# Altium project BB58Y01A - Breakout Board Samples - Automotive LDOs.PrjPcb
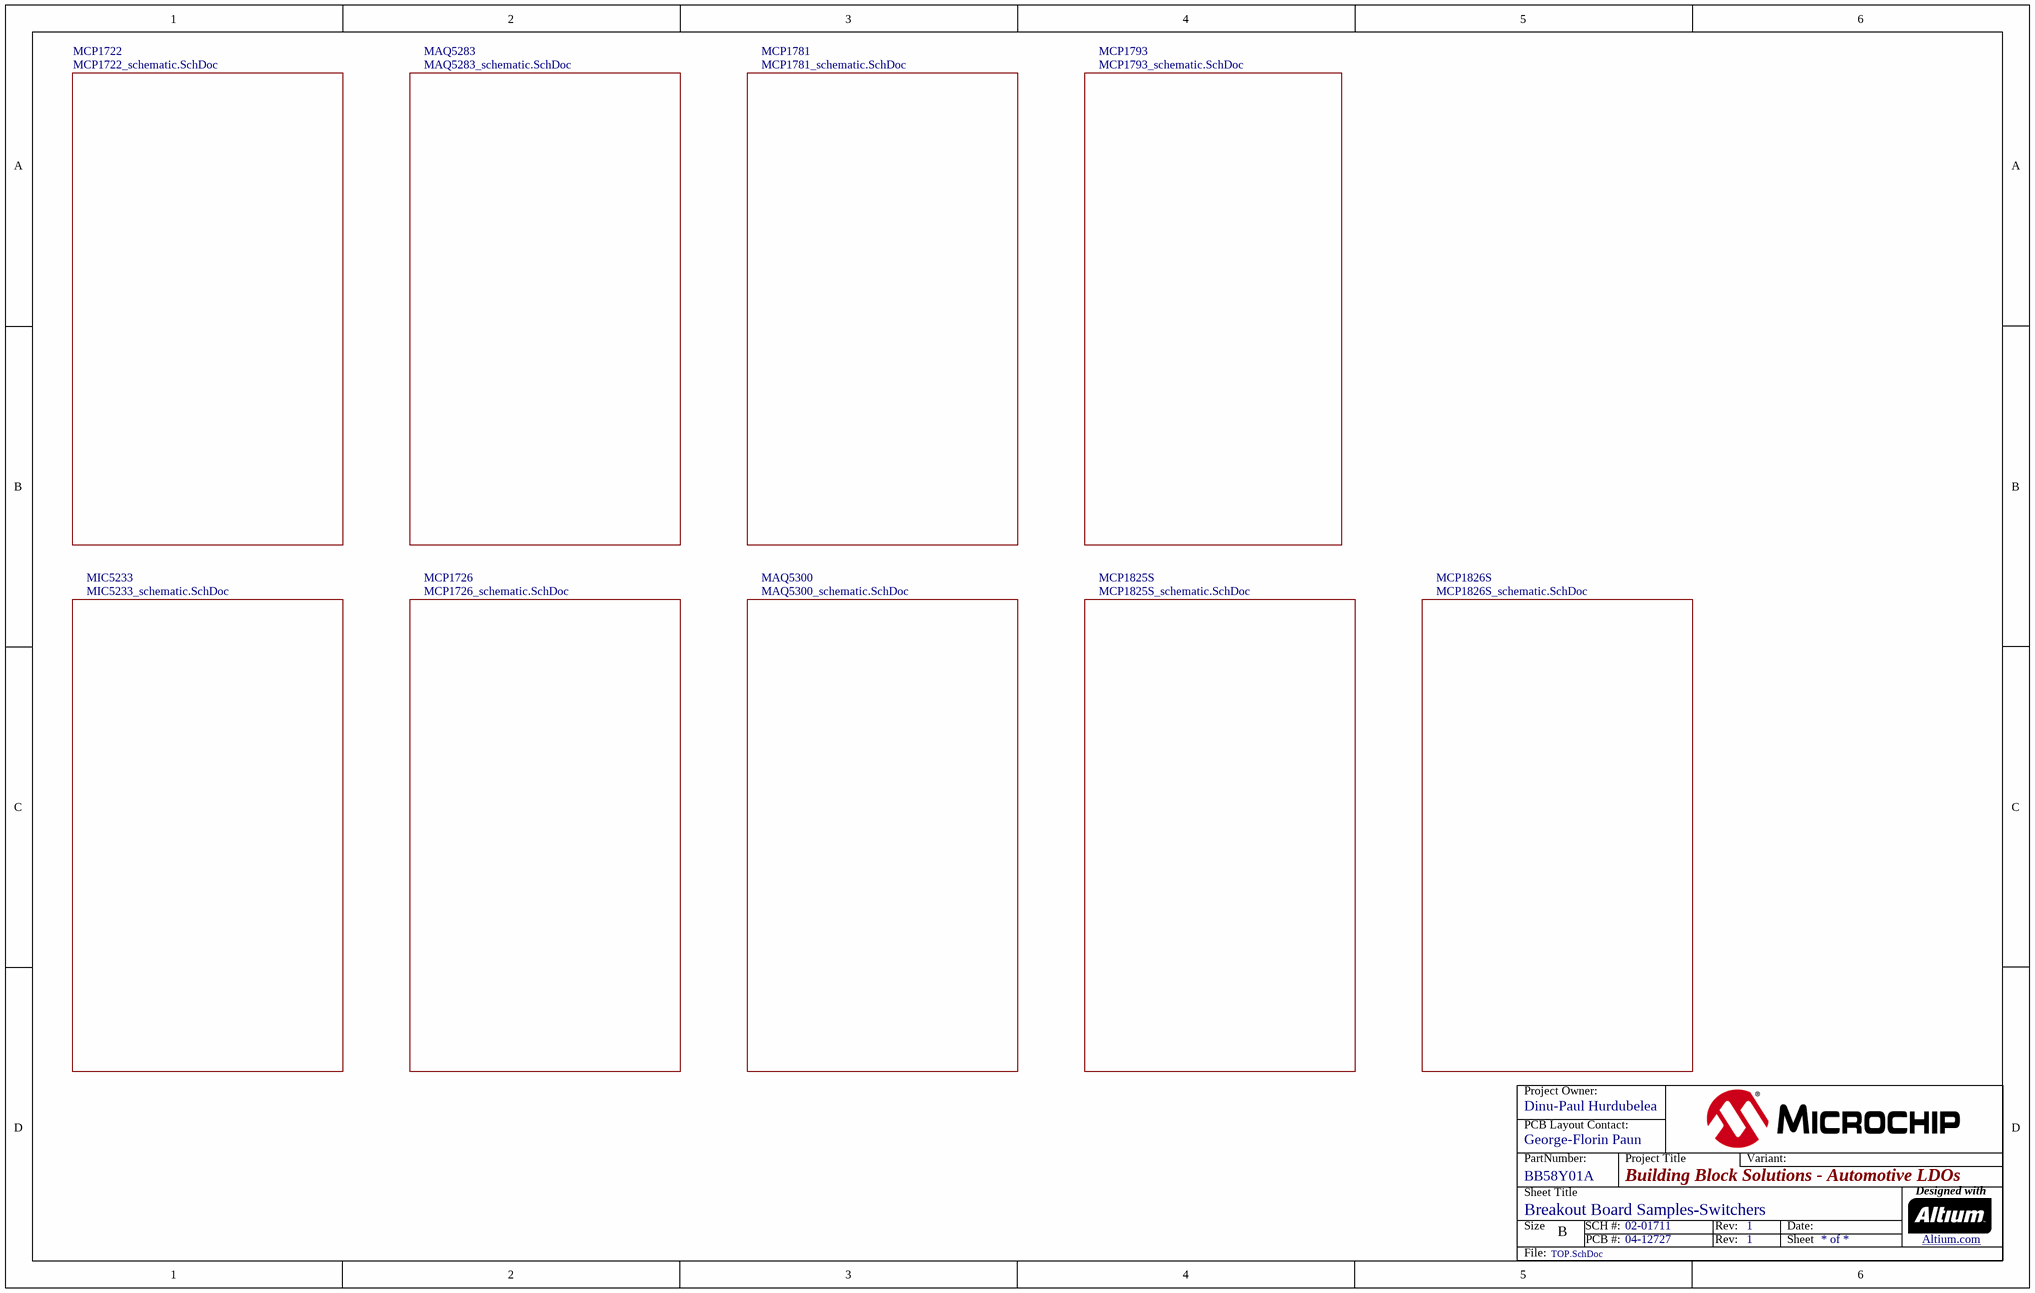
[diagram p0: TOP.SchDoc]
ProjectTitle: Building Block Solutions - Automotive LDOs; ProjectPCBFabRevision: 1; ProjectPCBFabNumber: 04-12727; ProjectPCBAssyRevision: 1; ProjectPCBAssyNumber: 02-01711; ProjectPartNumber: BB58Y01A; ProjectContactPCB: George-Florin Paun; ProjectContactOwner: Dinu-Paul Hurdubelea
10 sheets, 64 parts. Net scope: global (net labels, ports and power ports of the same name join across sheets).
Board file: 04-12242.PcbDoc
Sheets:
  TOP.SchDoc
    MAQ5283 = MAQ5283_schematic.SchDoc
    MCP1781 = MCP1781_schematic.SchDoc
    MIC5233 = MIC5233_schematic.SchDoc
    MCP1726 = MCP1726_schematic.SchDoc
    MAQ5300 = MAQ5300_schematic.SchDoc
    MCP1793 = MCP1793_schematic.SchDoc
    MCP1722 = MCP1722_schematic.SchDoc
    MCP1825S = MCP1825S_schematic.SchDoc
    MCP1826S = MCP1826S_schematic.SchDoc

## Sheet TOP.SchDoc
size B; CompanyName: Microchip Technology Inc.; Organization: Microchip Technology; Address1: 2355 West Chandler Blvd.; Address2: Chandler, AZ  85224; Address4: USA; SheetTitle: Breakout Board Samples-Switchers

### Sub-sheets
MAQ5283 = MAQ5283_schematic.SchDoc: no entries
MAQ5300 = MAQ5300_schematic.SchDoc: no entries
MCP1722 = MCP1722_schematic.SchDoc: no entries
MCP1726 = MCP1726_schematic.SchDoc: no entries
MCP1781 = MCP1781_schematic.SchDoc: no entries
MCP1793 = MCP1793_schematic.SchDoc: no entries
MCP1825S = MCP1825S_schematic.SchDoc: no entries
MCP1826S = MCP1826S_schematic.SchDoc: no entries
MIC5233 = MIC5233_schematic.SchDoc: no entries

## Sheet MAQ5283_schematic.SchDoc
size A4; SheetTitle: Vin:1.5V ; Vo:3.3V ; Io: 100 mA; CompanyName: Microchip Technology Inc.; Organization: Microchip Technology; Address1: 2355 West Chandler Blvd.; Address2: Chandler, AZ  85224; Address4: USA; DocumentNumber: 1; SheetNumber: 1; SheetTotal: 8
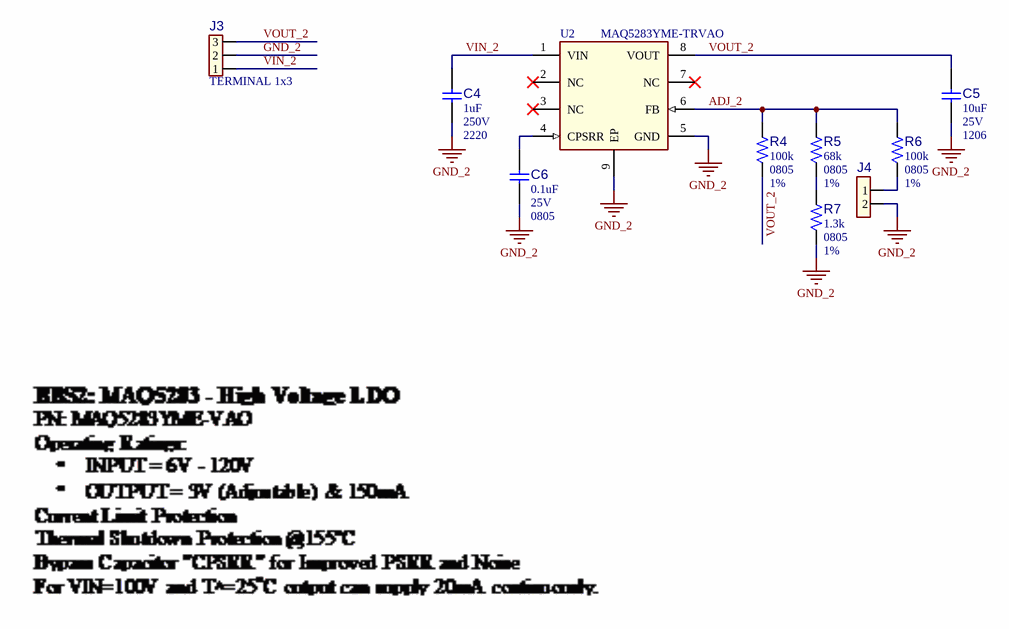
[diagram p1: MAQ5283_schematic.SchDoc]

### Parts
C4  value 1uF  Voltage: 250V  Package: 2220  [CAP_C_2220]  (hidden comment: Capacitor NP)
C5  value 10uF  Voltage: 25V  Package: 1206  [CAP_C_1206]  (hidden comment: Capacitor NP)
C6  value 0.1uF  Voltage: 25V  Package: 0805  [CAP_C_0805]  (hidden comment: Capacitor NP)
J3  value TERMINAL 1x3  [CON_TERMINAL_2.54_1x3_TH_RA_WE]  (hidden comment: Header 1x3)
J4  Header 1x2  [HDR_M_2.54_1x2]  (value not drawn)
R4  value 100k  Package: 0805  Tolerance: 1%  [RES_C_0805]  (hidden comment: Resistor)
R5  value 68k  Package: 0805  Tolerance: 1%  [RES_C_0805]  (hidden comment: Resistor)
R6  value 100k  Package: 0805  Tolerance: 1%  [RES_C_0805]  (hidden comment: Resistor)
R7  value 1.3k  Package: 0805  Tolerance: 1%  [RES_C_0805]  (hidden comment: Resistor)
U2  value MAQ5283YME-TRVAO  [SOIC-8_EP2.41x3.1]  (hidden comment: MAQ5283_SOIC-8)

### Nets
GND_2: C4.1 C5.1 C6.1 J3.2 J4.2 R7.1 U2.5(GND) U2.9(EP)
ADJ_2: R4.2 R5.2 R6.2 U2.6(FB)
VIN_2: C4.2 J3.1 U2.1(VIN)
VOUT_2: C5.2 J3.3 R4.1 U2.8(VOUT)
NetC6_2: C6.2 U2.4(CPSRR)
NetJ4_1: J4.1 R6.1
NetR5_1: R5.1 R7.2

Not connected (* = marked no-connect by the designer): U2 2(NC)* 3(NC)* 7(NC)*

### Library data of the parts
C4 = CAP3266: Manufacturer 1: Wuerth Elektronik; Manufacturer Part Number 1: 885342214002; Description_: CAP CER 1uF 250V 10% X7R SMD 2220; Dev Tools Status: Design; Tolerance: 10%; Temperature Coefficient: X7R; Type: Ceramic; Owner: Bianca Nastase; Populated: YES; Restricted Sourcing: No
C5 = CAP2272: Manufacturer 1: Würth Elektronik; Manufacturer Part Number 1: 885012208069; Description_: CAP CER 10uF 25V 10% X7R SMD 1206; Dev Tools Status: Production; Tolerance: 10%; Temperature Coefficient: X7R; Type: Ceramic; Owner: Octavian Stroe; Populated: YES; Restricted Sourcing: No
C6 = CAP3267: Manufacturer 1: Wuerth Elektronik; Manufacturer Part Number 1: 885012207072; Description_: CAP CER 0.1uF 25V 10% X7R SMD 0805; Dev Tools Status: Design; Tolerance: 10%; Temperature Coefficient: X7R; Type: Ceramic; Owner: Bianca Nastase; Populated: Yes; Restricted Sourcing: No
J3 = CON3164: Manufacturer 1: Wuerth Elektronik; Manufacturer Part Number 1: 691210910003; Description_: CON TERMINAL 2.54mm 1x3 Female 18-30AWG 6A TH R/A; Dev Tools Status: Design; Owner: Bianca Nastase; Voltage: 150V; Current: 6A; Populated: YES; Restricted Sourcing: No
J4 = CON1108: Manufacturer 1: Amphenol ICC (FCI); Manufacturer Part Number 1: 68001-202HLF; Value: HDR-2.54 Male 1x2; Description_: CON HDR-2.54 Male 1x2 Gold 5.84MH TH VERT; Dev Tools Status: Production; Owner: Bogdan P (M91398); Populated: Yes; Restricted Sourcing: No
R4 R6 = RES3525: Manufacturer 1: KOA Speer; Manufacturer Part Number 1: RK73H2ATTD1003F; Description_: RES TKF 100k 1% 1/4W SMD 0805 AEC-Q200; Dev Tools Status: Design; Temperature Coefficient: 100ppm/C; Power: 1/4W; Owner: Bianca Nastase; Populated: YES; Restricted Sourcing: No
R5 = RES2951: Manufacturer 1: TE Connectivity Passive Product; Manufacturer Part Number 1: CRGCQ0805F68K; Description_: RES TKF 68k 1% 1/8W SMD 0805 AEC-Q200; Dev Tools Status: Design; Voltage: 150V; Temperature Coefficient: 100ppm/C; Power: 1/8W; Owner: Florin Paun; Populated: YES; Restricted Sourcing: No
R7 = RES1416: Manufacturer 1: Yageo; Manufacturer Part Number 1: RC0805FR-071K3L; Description_: RES TKF 1.3k 1% 1/8W SMD 0805; Dev Tools Status: Production; Voltage: 150V; Temperature Coefficient: 100ppm/C; Circuit Type: Isolated; Power: 1/8W; Owner: Jairuz Agang-ang; Populated: YES
U2 = IC3036: Manufacturer 1: Microchip Technology; MCHP-ID: IC3036; Description_: MCHP ANALOG VOLTAGE REG 1.2V to 5.5V MAQ5283 SOIC-8 AEC-Q100; Dev Tools Status: Design; Owner: Florin Paun; Populated: YES; Restricted Sourcing: No

## Sheet MCP1781_schematic.SchDoc
size A4; SheetTitle: Vin:1.5V ;Vo:3.3V, Io:200 mA; CompanyName: Microchip Technology Inc.; Organization: Microchip Technology; Address1: 2355 West Chandler Blvd.; Address2: Chandler, AZ  85224; Address4: USA; DocumentNumber: 3; SheetNumber: 3; SheetTotal: 8
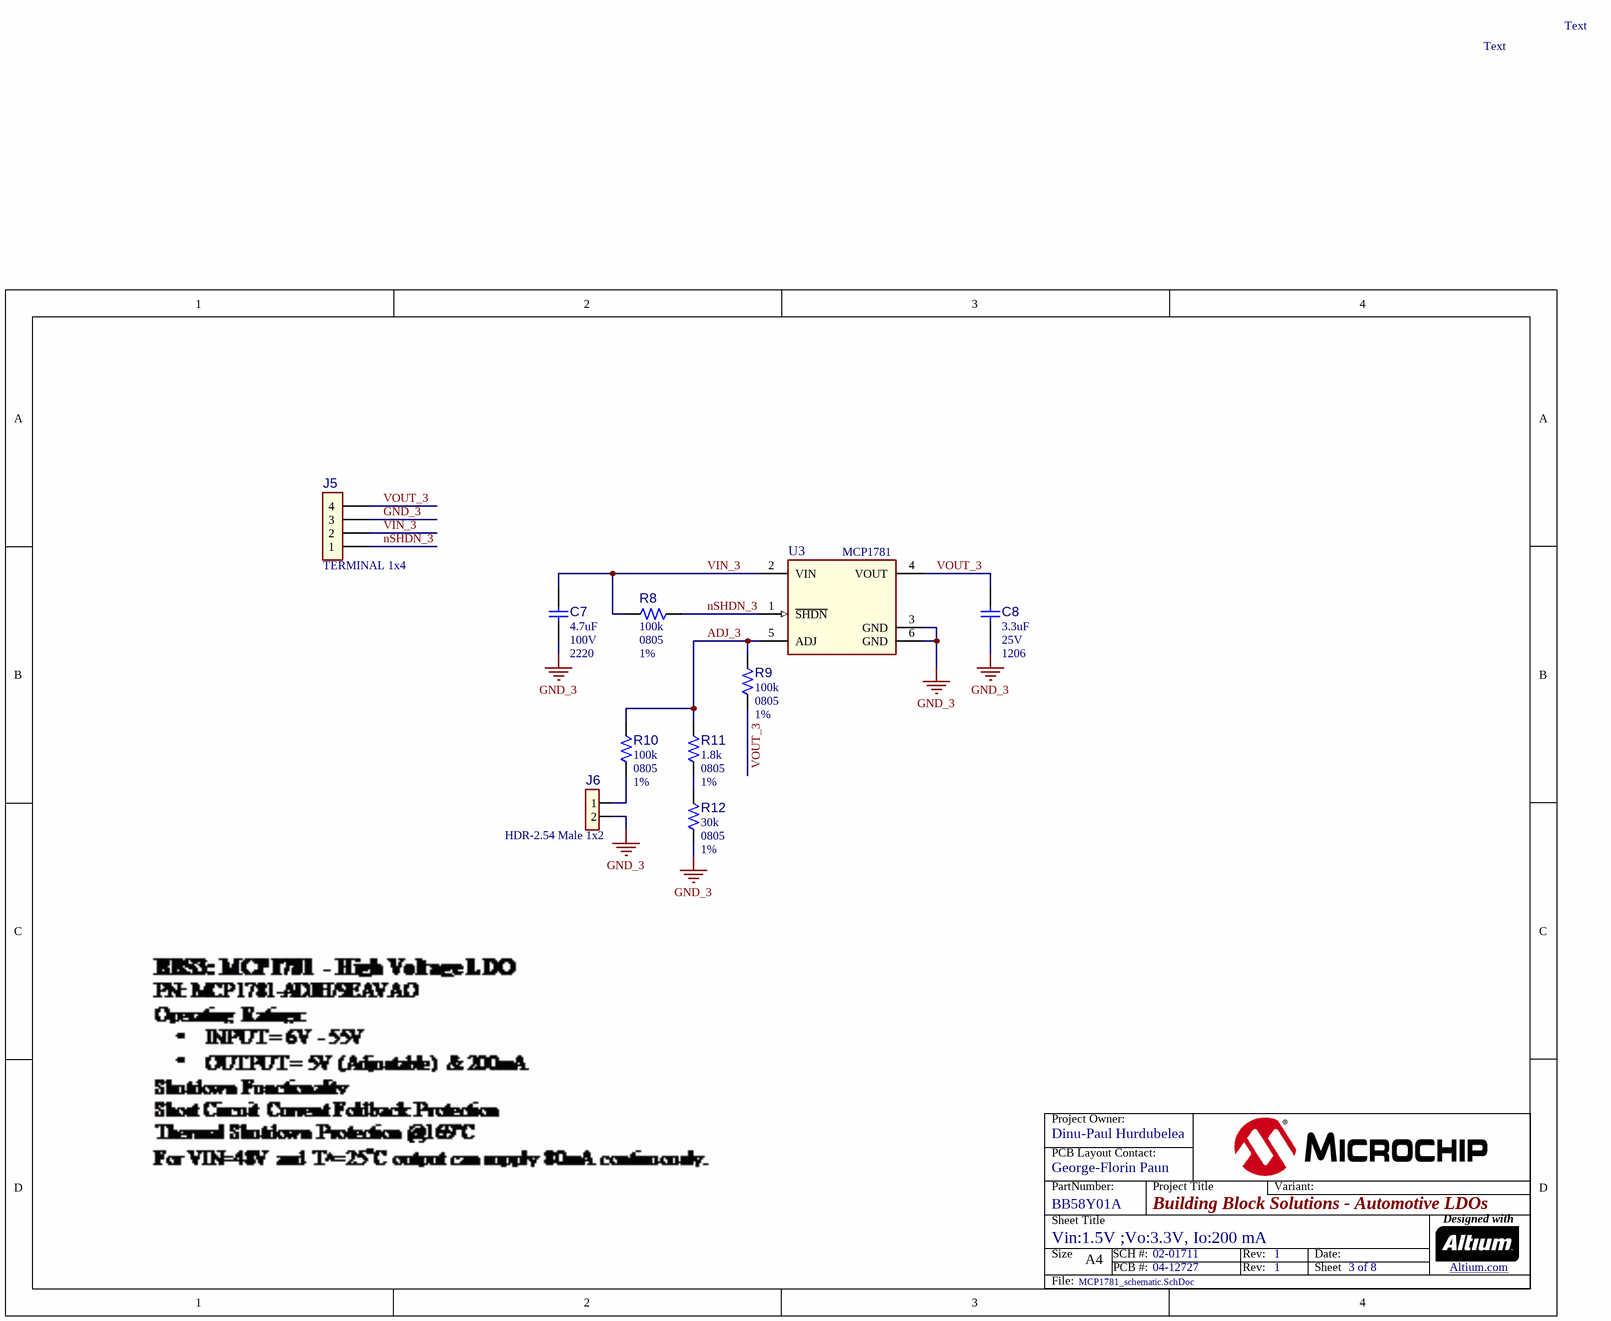
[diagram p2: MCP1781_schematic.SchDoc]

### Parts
C7  value 4.7uF  Voltage: 100V  Package: 2220  [CAP_C_2220]  (hidden comment: Capacitor NP)
C8  value 3.3uF  Voltage: 25V  Package: 1206  [CAP_C_1206]  (hidden comment: Capacitor NP)
J5  value TERMINAL 1x4  [CON_TERMINAL_2.54_1x4_TH_RA_WE]  (hidden comment: Header 1x4)
J6  value HDR-2.54 Male 1x2  [HDR_M_2.54_1x2]  (hidden comment: Header 1x2)
R8  value 100k  Package: 0805  Tolerance: 1%  [RES_C_0805]  (hidden comment: Resistor)
R9  value 100k  Package: 0805  Tolerance: 1%  [RES_C_0805]  (hidden comment: Resistor)
R10  value 100k  Package: 0805  Tolerance: 1%  [RES_C_0805]  (hidden comment: Resistor)
R11  value 1.8k  Package: 0805  Tolerance: 1%  [RES_C_0805]  (hidden comment: Resistor)
R12  value 30k  Package: 0805  Tolerance: 1%  [RES_C_0805]  (hidden comment: Resistor)
U3  value MCP1781  [TO-252-5_5pins]  (hidden comment: MCP1781 SOT-223-5_ADJ)

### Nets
GND_3: C7.1 C8.1 J5.3 J6.2 R12.1 U3.3(GND) U3.6(GND)
ADJ_3: R9.2 R10.2 R11.2 U3.5(ADJ)
nSHDN_3: J5.1 R8.1 U3.1(~{SHDN})
VIN_3: C7.2 J5.2 R8.2 U3.2(VIN)
VOUT_3: C8.2 J5.4 R9.1 U3.4(VOUT)
NetJ6_1: J6.1 R10.1
NetR11_1: R11.1 R12.2

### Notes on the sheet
- Text

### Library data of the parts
C7 = CAP0569: Manufacturer 1: Wuerth Elektronik; Manufacturer Part Number 1: 885012214003; Description_: CAP CER 4.7uF 100V 10% X7R SMD 2220; Dev Tools Status: Production; Tolerance: 10%; Temperature Coefficient: X7R; Type: Ceramic; Populated: Yes; Restricted Sourcing: No
C8 = CAP3265: Manufacturer 1: Wuerth Elektronik; Manufacturer Part Number 1: 885012208067; Description_: CAP CER 3.3uF 25V 10% X7R SMD 1206; Dev Tools Status: Design; Tolerance: 10%; Temperature Coefficient: X7R; Type: Ceramic; Owner: Bianca Nastase; Populated: YES; Restricted Sourcing: No
J5 = CON3130: Manufacturer 1: Wuerth Elektronik; Manufacturer Part Number 1: 691210910004; Description_: CON TERMINAL 2.54mm 1x4 Female 18-30AWG 6A TH R/A; Dev Tools Status: Design; Owner: Florin Paun; Voltage: 150V; Current: 6A; Populated: YES; Restricted Sourcing: No
J6 = CON1108: Manufacturer 1: Amphenol ICC (FCI); Manufacturer Part Number 1: 68001-202HLF; Description_: CON HDR-2.54 Male 1x2 Gold 5.84MH TH VERT; Dev Tools Status: Production; Owner: Bogdan P (M91398); Populated: Yes; Restricted Sourcing: No
R8-R10 = RES3525: as R4 on sheet MAQ5283_schematic
R11 = RSMT0599: Manufacturer 1: Panasonic; Manufacturer Part Number 1: ERJ-6ENF1801V; Description_: RES TKF 1.8k 1% 1/8W SMD 0805; Dev Tools Status: Production; Voltage: 150V; Temperature Coefficient: 100ppm/C; Power: 1/8W; Populated: Yes
R12 = RSMT0525: Manufacturer 1: Panasonic; Manufacturer Part Number 1: ERJ-6ENF3002V; Description_: RES TKF 30k 1% 1/8W SMD 0805; Dev Tools Status: Production; Voltage: 150V; Temperature Coefficient: 100ppm/C; Power: 1/8W; Populated: Yes
U3 = IC2880: LDO; Manufacturer 1: Microchip Technology; Manufacturer Part Number 1: MCP1781-ADJH/9EAVAO; MCHP-ID: IC2880; Description_: MCHP ANALOG LDO ADJ MCP1781 TO-252-5 AEC-Q100; Dev Tools Status: Design; Owner: Bianca Nastase; Populated: YES

## Sheet MIC5233_schematic.SchDoc
size A4; SheetTitle: Vin: 2.4-5.5V; Vo:24V; Io: 150mA; CompanyName: Microchip Technology Inc.; Organization: Microchip Technology; Address1: 2355 West Chandler Blvd.; Address2: Chandler, AZ  85224; Address4: USA; DocumentNumber: 5; SheetNumber: 5; SheetTotal: 8
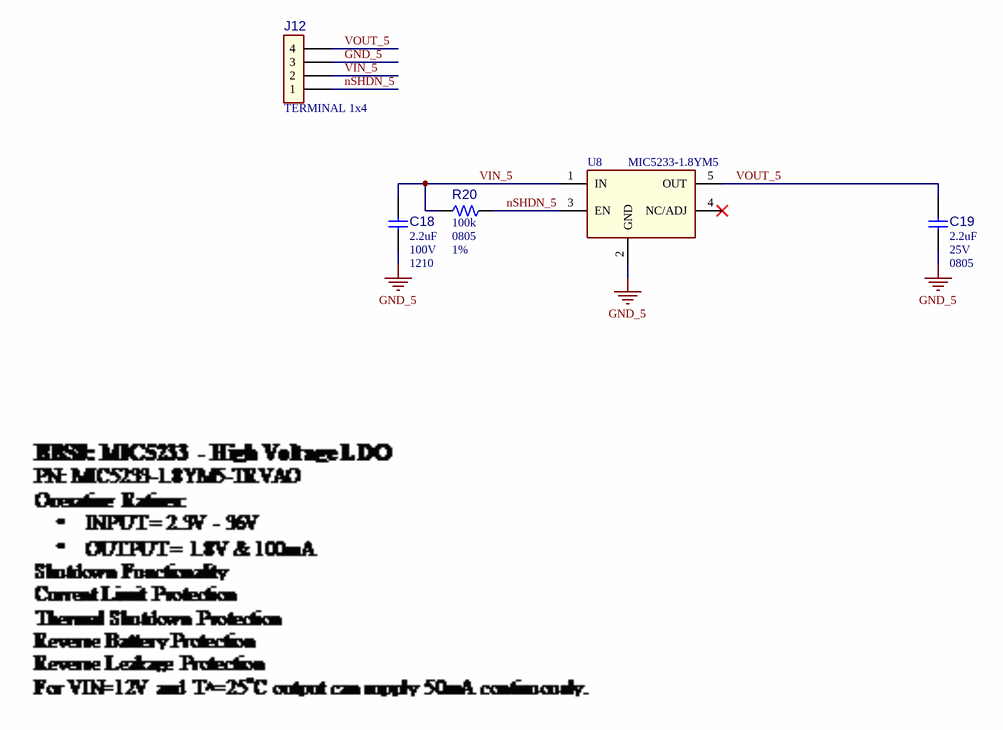
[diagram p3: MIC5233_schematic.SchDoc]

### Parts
C18  value 2.2uF  Voltage: 100V  Package: 1210  [CAP_C_1210]  (hidden comment: Capacitor NP)
C19  value 2.2uF  Voltage: 25V  Package: 0805  [CAP_C_0805]  (hidden comment: Capacitor NP)
J12  value TERMINAL 1x4  [CON_TERMINAL_2.54_1x4_TH_RA_WE]  (hidden comment: Header 1x4)
R20  value 100k  Package: 0805  Tolerance: 1%  [RES_C_0805]  (hidden comment: Resistor)
U8  value MIC5233-1.8YM5  [SOT-23-5]  (hidden comment: MIC5233 SOT-23-5)

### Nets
GND_5: C18.1 C19.1 J12.3 U8.2(GND)
nSHDN_5: J12.1 R20.2 U8.3(EN)
VIN_5: C18.2 J12.2 R20.1 U8.1(IN)
VOUT_5: C19.2 J12.4 U8.5(OUT)

Not connected (* = marked no-connect by the designer): U8 4(NC/ADJ)*

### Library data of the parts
C18 = CAP2455: Manufacturer 1: Murata; Manufacturer Part Number 1: GRM32ER72A225KA35K; Description_: CAP CER 2.2uF 100V 10% X7R SMD 1210; Dev Tools Status: Production; Tolerance: 10%; Temperature Coefficient: X7R; Type: Ceramic; Owner: Mihai T(M91442); Populated: YES; Restricted Sourcing: No
C19 = CAP2292: Manufacturer 1: Würth Elektronik; Manufacturer Part Number 1: 885012207079; Description_: CAP CER 2.2uF 25V 10% X7R SMD 0805; Dev Tools Status: Production; Tolerance: 10%; Temperature Coefficient: X7R; Type: Ceramic; Owner: Narasimha Murthy; Populated: YES; Restricted Sourcing: No
J12 = CON3130: as J5 on sheet MCP1781_schematic
R20 = RES3525: as R4 on sheet MAQ5283_schematic
U8 = IC3071: Manufacturer 1: Microchip Technology; Manufacturer Part Number 1: MIC5233-1.8YM5-TRVAO; MCHP-ID: IC3071; Description_: MCHP ANALOG LDO 1.8V MIC5233-1.8YM5-TRVAO SOT-23-5  AEC-Q100; Dev Tools Status: Design; Owner: Bianca Nastase; Populated: YES; Restricted Sourcing: No

## Sheet MCP1726_schematic.SchDoc
size A4; SheetTitle: Vin:2.4-5.5V ; Vout:_V ; Io: 100mA; CompanyName: Microchip Technology Inc.; Organization: Microchip Technology; Address1: 2355 West Chandler Blvd.; Address2: Chandler, AZ  85224; Address4: USA; DocumentNumber: 6; SheetNumber: 6; SheetTotal: 8
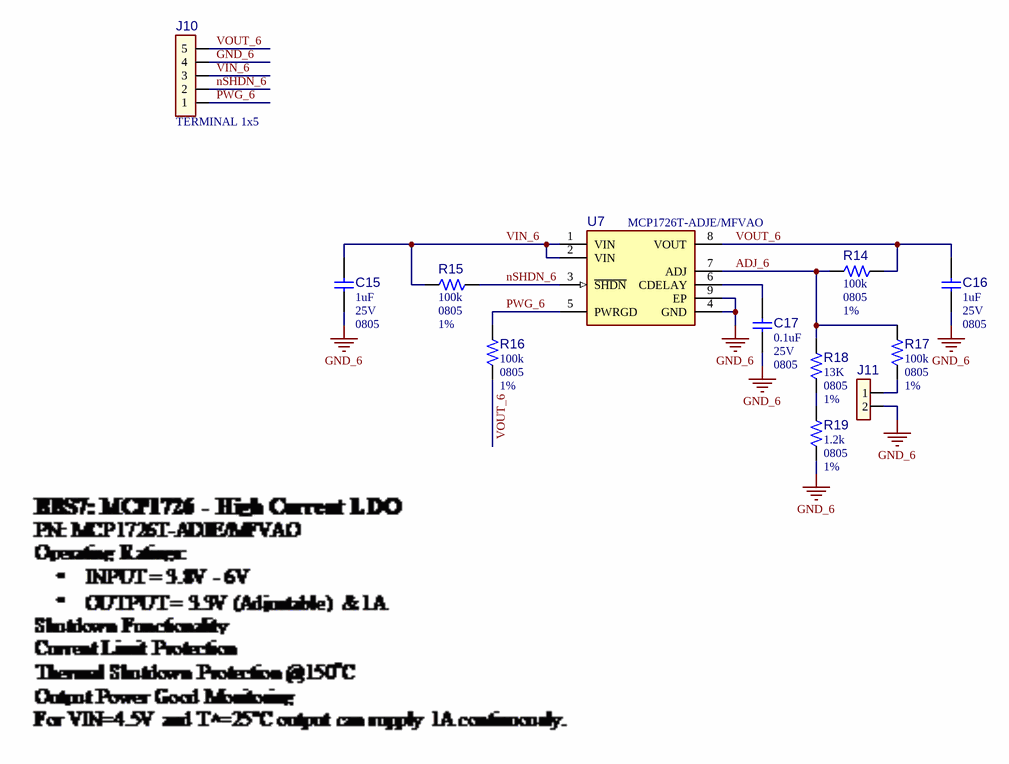
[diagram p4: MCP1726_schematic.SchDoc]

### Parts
C15  value 1uF  Voltage: 25V  Package: 0805  [CAP_C_0805]  (hidden comment: Capacitor NP)
C16  value 1uF  Voltage: 25V  Package: 0805  [CAP_C_0805]  (hidden comment: Capacitor NP)
C17  value 0.1uF  Voltage: 25V  Package: 0805  [CAP_C_0805]  (hidden comment: Capacitor NP)
J10  value TERMINAL 1x5  [CON_TERMINAL_2.54_1x5_TH_RA_WE]  (hidden comment: Header 1x5)
J11  Header 1x2  [HDR_M_2.54_1x2]  (value not drawn)
R14  value 100k  Package: 0805  Tolerance: 1%  [RES_C_0805]  (hidden comment: Resistor)
R15  value 100k  Package: 0805  Tolerance: 1%  [RES_C_0805]  (hidden comment: Resistor)
R16  value 100k  Package: 0805  Tolerance: 1%  [RES_C_0805]  (hidden comment: Resistor)
R17  value 100k  Package: 0805  Tolerance: 1%  [RES_C_0805]  (hidden comment: Resistor)
R18  value 13K  Package: 0805  Tolerance: 1%  [RES_C_0805]  (hidden comment: Resistor)
R19  value 1.2k  Package: 0805  Tolerance: 1%  [RES_C_0805]  (hidden comment: Resistor)
U7  value MCP1726T-ADJE/MFVAO  [DFN-8_3x3]  (hidden comment: MCP172X ADJ DFN-8)

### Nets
GND_6: C15.1 C16.1 C17.1 J10.4 J11.2 R19.1 U7.4(GND) U7.9(EP)
ADJ_6: R14.1 R17.2 R18.2 U7.7(ADJ)
nSHDN_6: J10.2 R15.2 U7.3(~{SHDN})
PWG_6: J10.1 R16.1 U7.5(PWRGD)
VIN_6: C15.2 J10.3 R15.1 U7.1(VIN) U7.2(VIN)
VOUT_6: C16.2 J10.5 R14.2 R16.2 U7.8(VOUT)
NetC17_2: C17.2 U7.6(CDELAY)
NetJ11_1: J11.1 R17.1
NetR18_1: R18.1 R19.2

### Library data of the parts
C15 C16 = CAP2456: Manufacturer 1: Wurth Electronics; Manufacturer Part Number 1: 885012207078; Description_: CAP CER 1uF 25V 10% X7R SMD 0805; Dev Tools Status: Design; Tolerance: 10%; Temperature Coefficient: X7R; Type: Ceramic; Owner: Cristina Salanti; Populated: YES
C17 = CAP3267: as C6 on sheet MAQ5283_schematic
J10 = CON3131: Manufacturer 1: Wuerth Elektronik; Manufacturer Part Number 1: 691210910005; Description_: CON TERMINAL 2.54mm 1x5 Female 18-30AWG 6A TH R/A; Dev Tools Status: Design; Owner: Florin Paun; Voltage: 150V; Current: 6A; Populated: YES; Restricted Sourcing: No
J11 = CON1108: as J4 on sheet MAQ5283_schematic
R14-R17 = RES3525: as R4 on sheet MAQ5283_schematic
R18 = RES2889: Manufacturer 1: Panasonic Electronic Components; Manufacturer Part Number 1: ERJ-U06F1302V; Description_: RES TKF 13k 1% 1/8W SMD 0805; Dev Tools Status: Production; Temperature Coefficient: ±100ppm/°C; Power: 1/8W; Owner: Lucian Buradel; Populated: YES; Restricted Sourcing: No
R19 = RSMT0237: Manufacturer 1: Yageo; Manufacturer Part Number 1: RC0805FR-071K2L; Description_: RES TKF 1.2k 1% 1/8W SMD 0805; Dev Tools Status: Production; Voltage: 150V; Temperature Coefficient: 100ppm/C; Power: 1/8W; Owner: Cristian Papuc; Populated: YES; Restricted Sourcing: No
U7 = IC3039: LDO ADJ; Manufacturer 1: Microchip Technology; MCHP-ID: IC3039; Description_: MCHP ANALOG LDO ADJ 0.8V-5V MCP1726 DFN-8 AEC-Q100; Dev Tools Status: Design; Owner: Florin Paun; Populated: YES; Restricted Sourcing: No

## Sheet MAQ5300_schematic.SchDoc
size A4; SheetTitle: Vin: 6-50V; Vout:5V ; Io:500 mA; CompanyName: Microchip Technology Inc.; Organization: Microchip Technology; Address1: 2355 West Chandler Blvd.; Address2: Chandler, AZ  85224; Address4: USA; DocumentNumber: 7; SheetNumber: 7; SheetTotal: 8
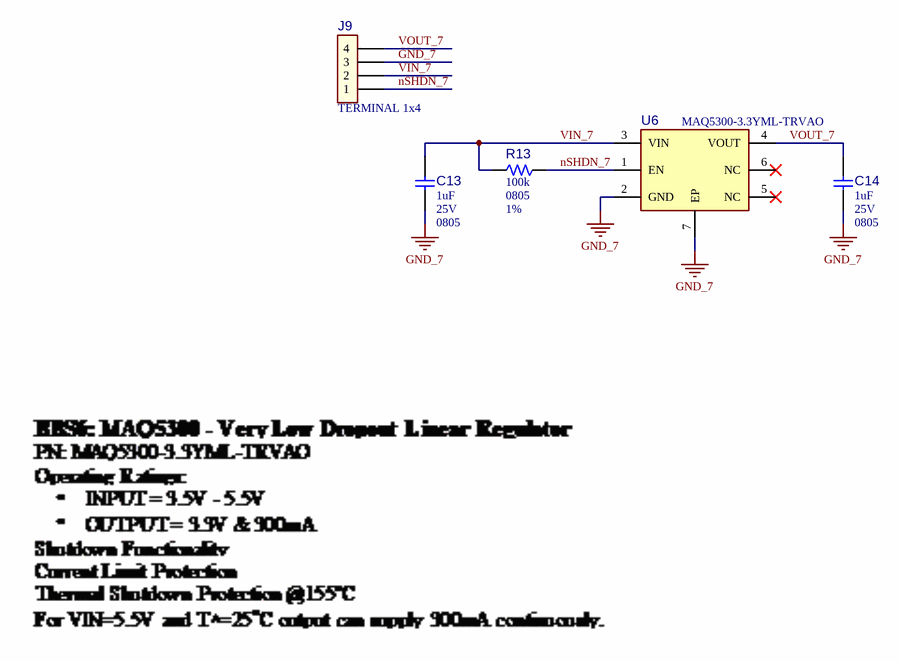
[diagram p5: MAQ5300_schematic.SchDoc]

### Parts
C13  value 1uF  Voltage: 25V  Package: 0805  [CAP_C_0805]  (hidden comment: Capacitor NP)
C14  value 1uF  Voltage: 25V  Package: 0805  [CAP_C_0805]  (hidden comment: Capacitor NP)
J9  value TERMINAL 1x4  [CON_TERMINAL_2.54_1x4_TH_RA_WE]  (hidden comment: Header 1x4)
R13  value 100k  Package: 0805  Tolerance: 1%  [RES_C_0805]  (hidden comment: Resistor)
U6  value MAQ5300-3.3YML-TRVAO  [DFN-6_2x2_EP1.7x0.9]  (hidden comment: MAQ5300 DFN-6)

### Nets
GND_7: C13.1 C14.1 J9.3 U6.2(GND) U6.7(EP)
nSHDN_7: J9.1 R13.2 U6.1(EN)
VIN_7: C13.2 J9.2 R13.1 U6.3(VIN)
VOUT_7: C14.2 J9.4 U6.4(VOUT)

Not connected (* = marked no-connect by the designer): U6 5(NC)* 6(NC)*

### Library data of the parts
C13 C14 = CAP2456: as C15 on sheet MCP1726_schematic
J9 = CON3130: as J5 on sheet MCP1781_schematic
R13 = RES3525: as R4 on sheet MAQ5283_schematic
U6 = IC3040: LDO; Manufacturer 1: Microchip Technology; MCHP-ID: IC3040; Description_: MCHP ANALOG LDO 3.3V 300mA MAQ5300 DFN-6 AEC-Q100; Dev Tools Status: Design; Owner: Florin Paun; Populated: YES; Restricted Sourcing: No

## Sheet MCP1793_schematic.SchDoc
size A4; SheetTitle: Vin: 2.4-5.5V;Vo:12V, Io: 200 mA; CompanyName: Microchip Technology Inc.; Organization: Microchip Technology; Address1: 2355 West Chandler Blvd.; Address2: Chandler, AZ  85224; Address4: USA; DocumentNumber: 4; SheetNumber: 4; SheetTotal: 8
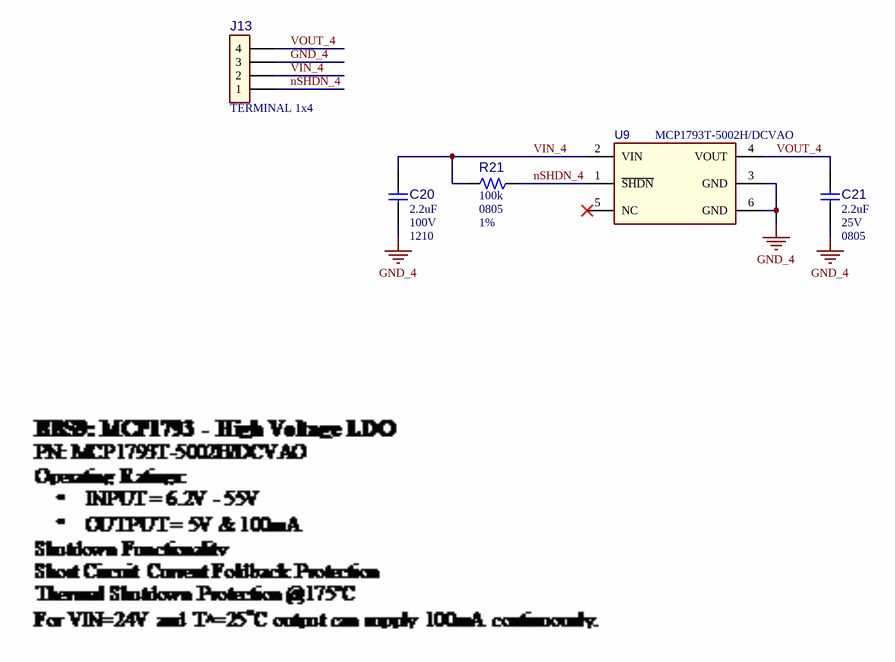
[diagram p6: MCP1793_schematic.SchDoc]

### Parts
C20  value 2.2uF  Voltage: 100V  Package: 1210  [CAP_C_1210]  (hidden comment: Capacitor NP)
C21  value 2.2uF  Voltage: 25V  Package: 0805  [CAP_C_0805]  (hidden comment: Capacitor NP)
J13  value TERMINAL 1x4  [CON_TERMINAL_2.54_1x4_TH_RA_WE]  (hidden comment: Header 1x4)
R21  value 100k  Package: 0805  Tolerance: 1%  [RES_C_0805]  (hidden comment: Resistor)
U9  value MCP1793T-5002H/DCVAO  [SOT-223-5]  (hidden comment: MCP1793T_SOT-223)

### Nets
GND_4: C20.1 C21.1 J13.3 U9.3(GND) U9.6(GND)
nSHDN_4: J13.1 R21.1 U9.1(~{SHDN})
VIN_4: C20.2 J13.2 R21.2 U9.2(VIN)
VOUT_4: C21.2 J13.4 U9.4(VOUT)

Not connected (* = marked no-connect by the designer): U9 5(NC)*

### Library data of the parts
C20 = CAP2455: as C18 on sheet MIC5233_schematic
C21 = CAP2292: as C19 on sheet MIC5233_schematic
J13 = CON3130: as J5 on sheet MCP1781_schematic
R21 = RES3525: as R4 on sheet MAQ5283_schematic
U9 = IC3037: Manufacturer 1: Microchip Technology; MCHP-ID: IC3037; Description_: MCHP ANALOG REG 5V MCP1793 SOT-223-5 AEC-Q100; Dev Tools Status: Design; Owner: Florin Paun; Populated: YES; Restricted Sourcing: No

## Sheet MCP1722_schematic.SchDoc
size A4; CompanyName: Microchip Technology Inc.; Organization: Microchip Technology; Address1: 2355 West Chandler Blvd.; Address2: Chandler, AZ  85224; Address4: USA; SheetTitle: **
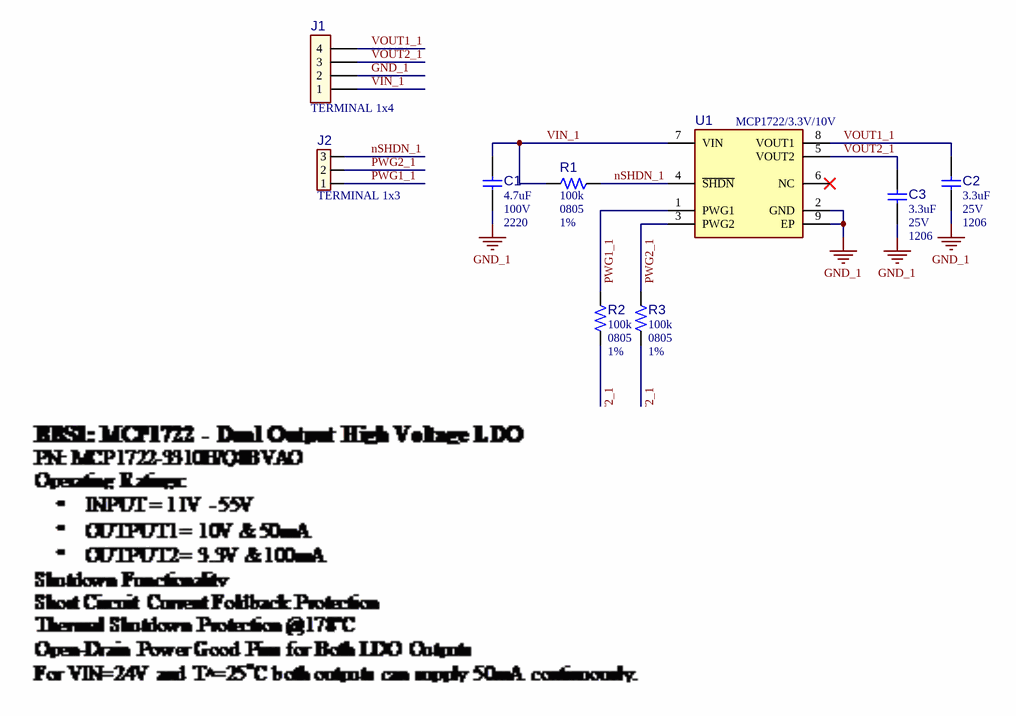
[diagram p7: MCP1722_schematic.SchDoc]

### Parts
C1  value 4.7uF  Voltage: 100V  Package: 2220  [CAP_C_2220]  (hidden comment: Capacitor NP)
C2  value 3.3uF  Voltage: 25V  Package: 1206  [CAP_C_1206]  (hidden comment: Capacitor NP)
C3  value 3.3uF  Voltage: 25V  Package: 1206  [CAP_C_1206]  (hidden comment: Capacitor NP)
J1  value TERMINAL 1x4  [CON_TERMINAL_2.54_1x4_TH_RA_WE]  (hidden comment: Header 1x4)
J2  value TERMINAL 1x3  [CON_TERMINAL_2.54_1x3_TH_RA_WE]  (hidden comment: Header 1x3)
R1  value 100k  Package: 0805  Tolerance: 1%  [RES_C_0805]  (hidden comment: Resistor)
R2  value 100k  Package: 0805  Tolerance: 1%  [RES_C_0805]  (hidden comment: Resistor)
R3  value 100k  Package: 0805  Tolerance: 1%  [RES_C_0805]  (hidden comment: Resistor)
U1  value MCP1722/3.3V/10V  [DFN-8_3x3]  (hidden comment: MCP1722_DFN-8_EP)

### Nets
GND_1: C1.1 C2.1 C3.1 J1.2 U1.2(GND) U1.9(EP)
nSHDN_1: J2.3 R1.1 U1.4(~{SHDN})
PWG1_1: J2.1 R2.2 U1.1(PWG1)
PWG2_1: J2.2 R3.2 U1.3(PWG2)
VIN_1: C1.2 J1.1 R1.2 U1.7(VIN)
VOUT1_1: C2.2 J1.4 U1.8(VOUT1)
VOUT2_1: C3.2 J1.3 R2.1 R3.1 U1.5(VOUT2)

Not connected (* = marked no-connect by the designer): U1 6(NC)*

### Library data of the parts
C1 = CAP0569: as C7 on sheet MCP1781_schematic
C2 C3 = CAP3265: as C8 on sheet MCP1781_schematic
J1 = CON3130: as J5 on sheet MCP1781_schematic
J2 = CON3164: as J3 on sheet MAQ5283_schematic
R1-R3 = RES3525: as R4 on sheet MAQ5283_schematic
U1 = IC3069: LDO; Manufacturer 1: Microchip Technology; Manufacturer Part Number 1: MCP1722-3310H/Q8BVAO; MCHP-ID: IC3069; Description_: MCHP ANALOG LDO 3.3V/10V MCP1722-3310H/Q8BVAO DFN-8 AEC-Q100; Dev Tools Status: Design; Owner: Bianca Nastase; Populated: YES; Restricted Sourcing: No

## Sheet MCP1825S_schematic.SchDoc
size A4; CompanyName: Microchip Technology Inc.; Organization: Microchip Technology; Address1: 2355 West Chandler Blvd.; Address2: Chandler, AZ  85224; Address4: USA; SheetTitle: **
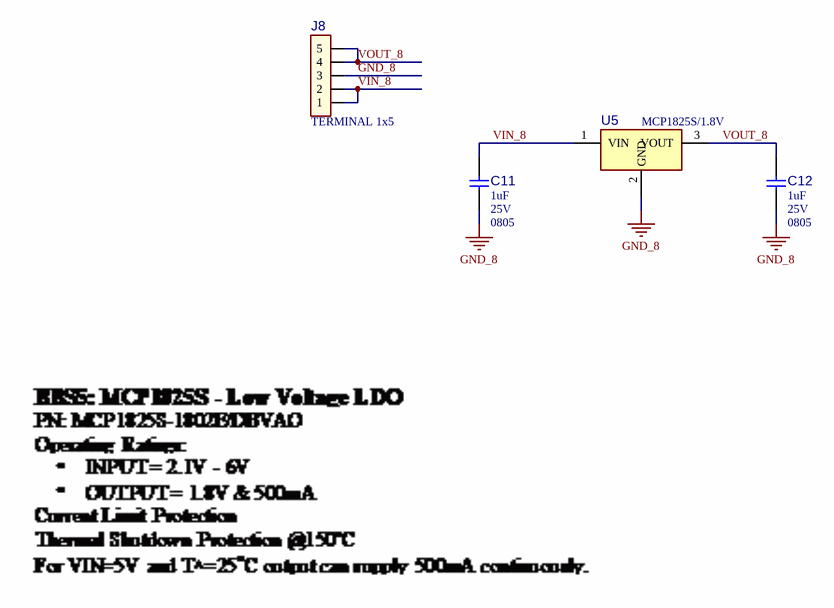
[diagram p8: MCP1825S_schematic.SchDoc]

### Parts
C11  value 1uF  Voltage: 25V  Package: 0805  [CAP_C_0805]  (hidden comment: Capacitor NP)
C12  value 1uF  Voltage: 25V  Package: 0805  [CAP_C_0805]  (hidden comment: Capacitor NP)
J8  value TERMINAL 1x5  [CON_TERMINAL_2.54_1x5_TH_RA_WE]  (hidden comment: Header 1x5)
U5  value MCP1825S/1.8V  [SOT-223-3]  (hidden comment: MIC39100 SOT-223-3)

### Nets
GND_8: C11.1 C12.1 J8.3 U5.2(GND)
VIN_8: C11.2 J8.1 J8.2 U5.1(VIN)
VOUT_8: C12.2 J8.4 J8.5 U5.3(VOUT)

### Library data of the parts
C11 C12 = CAP2456: as C15 on sheet MCP1726_schematic
J8 = CON3131: as J10 on sheet MCP1726_schematic
U5 = IC3079: LDO; Manufacturer 1: Microchip Technology; Manufacturer Part Number 1: MCP1825S-1802E/DBVAO; MCHP-ID: IC3079; Description_: MCHP ANALOG LDO 1.8V MCP1825S-1802E/DBVAO SOT-223-3 AEC-Q100; Dev Tools Status: Design; Populated: Yes; Owner: Bianca Nastase

## Sheet MCP1826S_schematic.SchDoc
size A4; CompanyName: Microchip Technology Inc.; Organization: Microchip Technology; Address1: 2355 West Chandler Blvd.; Address2: Chandler, AZ  85224; Address4: USA; SheetTitle: **
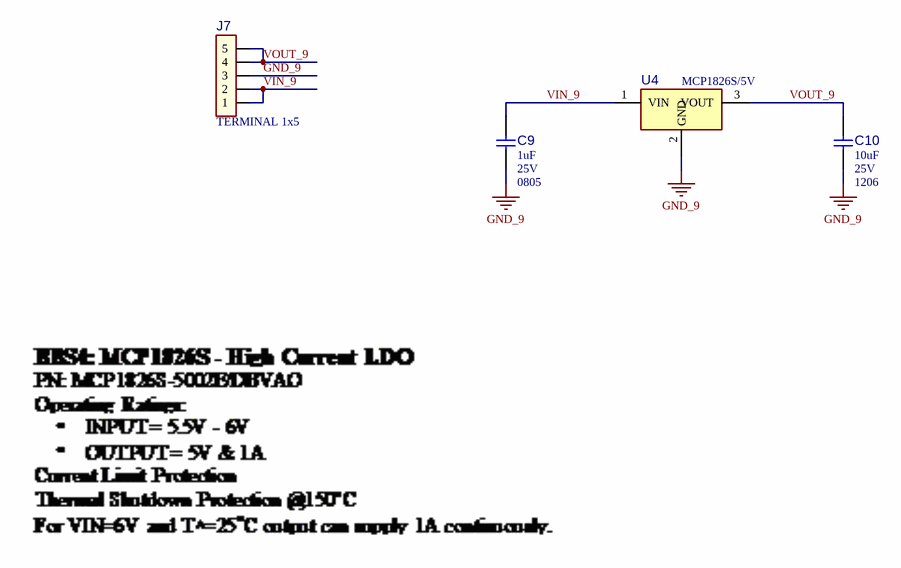
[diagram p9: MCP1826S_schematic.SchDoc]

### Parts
C9  value 1uF  Voltage: 25V  Package: 0805  [CAP_C_0805]  (hidden comment: Capacitor NP)
C10  value 10uF  Voltage: 25V  Package: 1206  [CAP_C_1206]  (hidden comment: Capacitor NP)
J7  value TERMINAL 1x5  [CON_TERMINAL_2.54_1x5_TH_RA_WE]  (hidden comment: Header 1x5)
U4  value MCP1826S/5V  [SOT-223-3]  (hidden comment: MIC39100 SOT-223-3)

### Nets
GND_9: C9.1 C10.1 J7.3 U4.2(GND)
VIN_9: C9.2 J7.1 J7.2 U4.1(VIN)
VOUT_9: C10.2 J7.4 J7.5 U4.3(VOUT)

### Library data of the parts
C9 = CAP2456: as C15 on sheet MCP1726_schematic
C10 = CAP2272: as C5 on sheet MAQ5283_schematic
J7 = CON3131: as J10 on sheet MCP1726_schematic
U4 = IC3072: LDO; Manufacturer 1: Microchip Technology; Manufacturer Part Number 1: MCP1826S-5002E/DBVAO; MCHP-ID: IC3072; Description_: MCHP ANALOG LDO 5V MCP1826S-5002E/DBVAO SOT-223-3 AEC-Q100; Dev Tools Status: Design; Owner: Bianca Nastase; Populated: Yes

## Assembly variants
V1: not fitted J4 J6 J11 R6 R10 R18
